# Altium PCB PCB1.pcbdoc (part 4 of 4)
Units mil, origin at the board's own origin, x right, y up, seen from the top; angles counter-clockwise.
Board outline 2559.1 x 3937 mil, 4 copper layers (Top Layer, Inner1, Inner2, Bottom Layer), stack 102.8 mil thick; 377 components, 358 nets, 1639 pads, 361 vias.
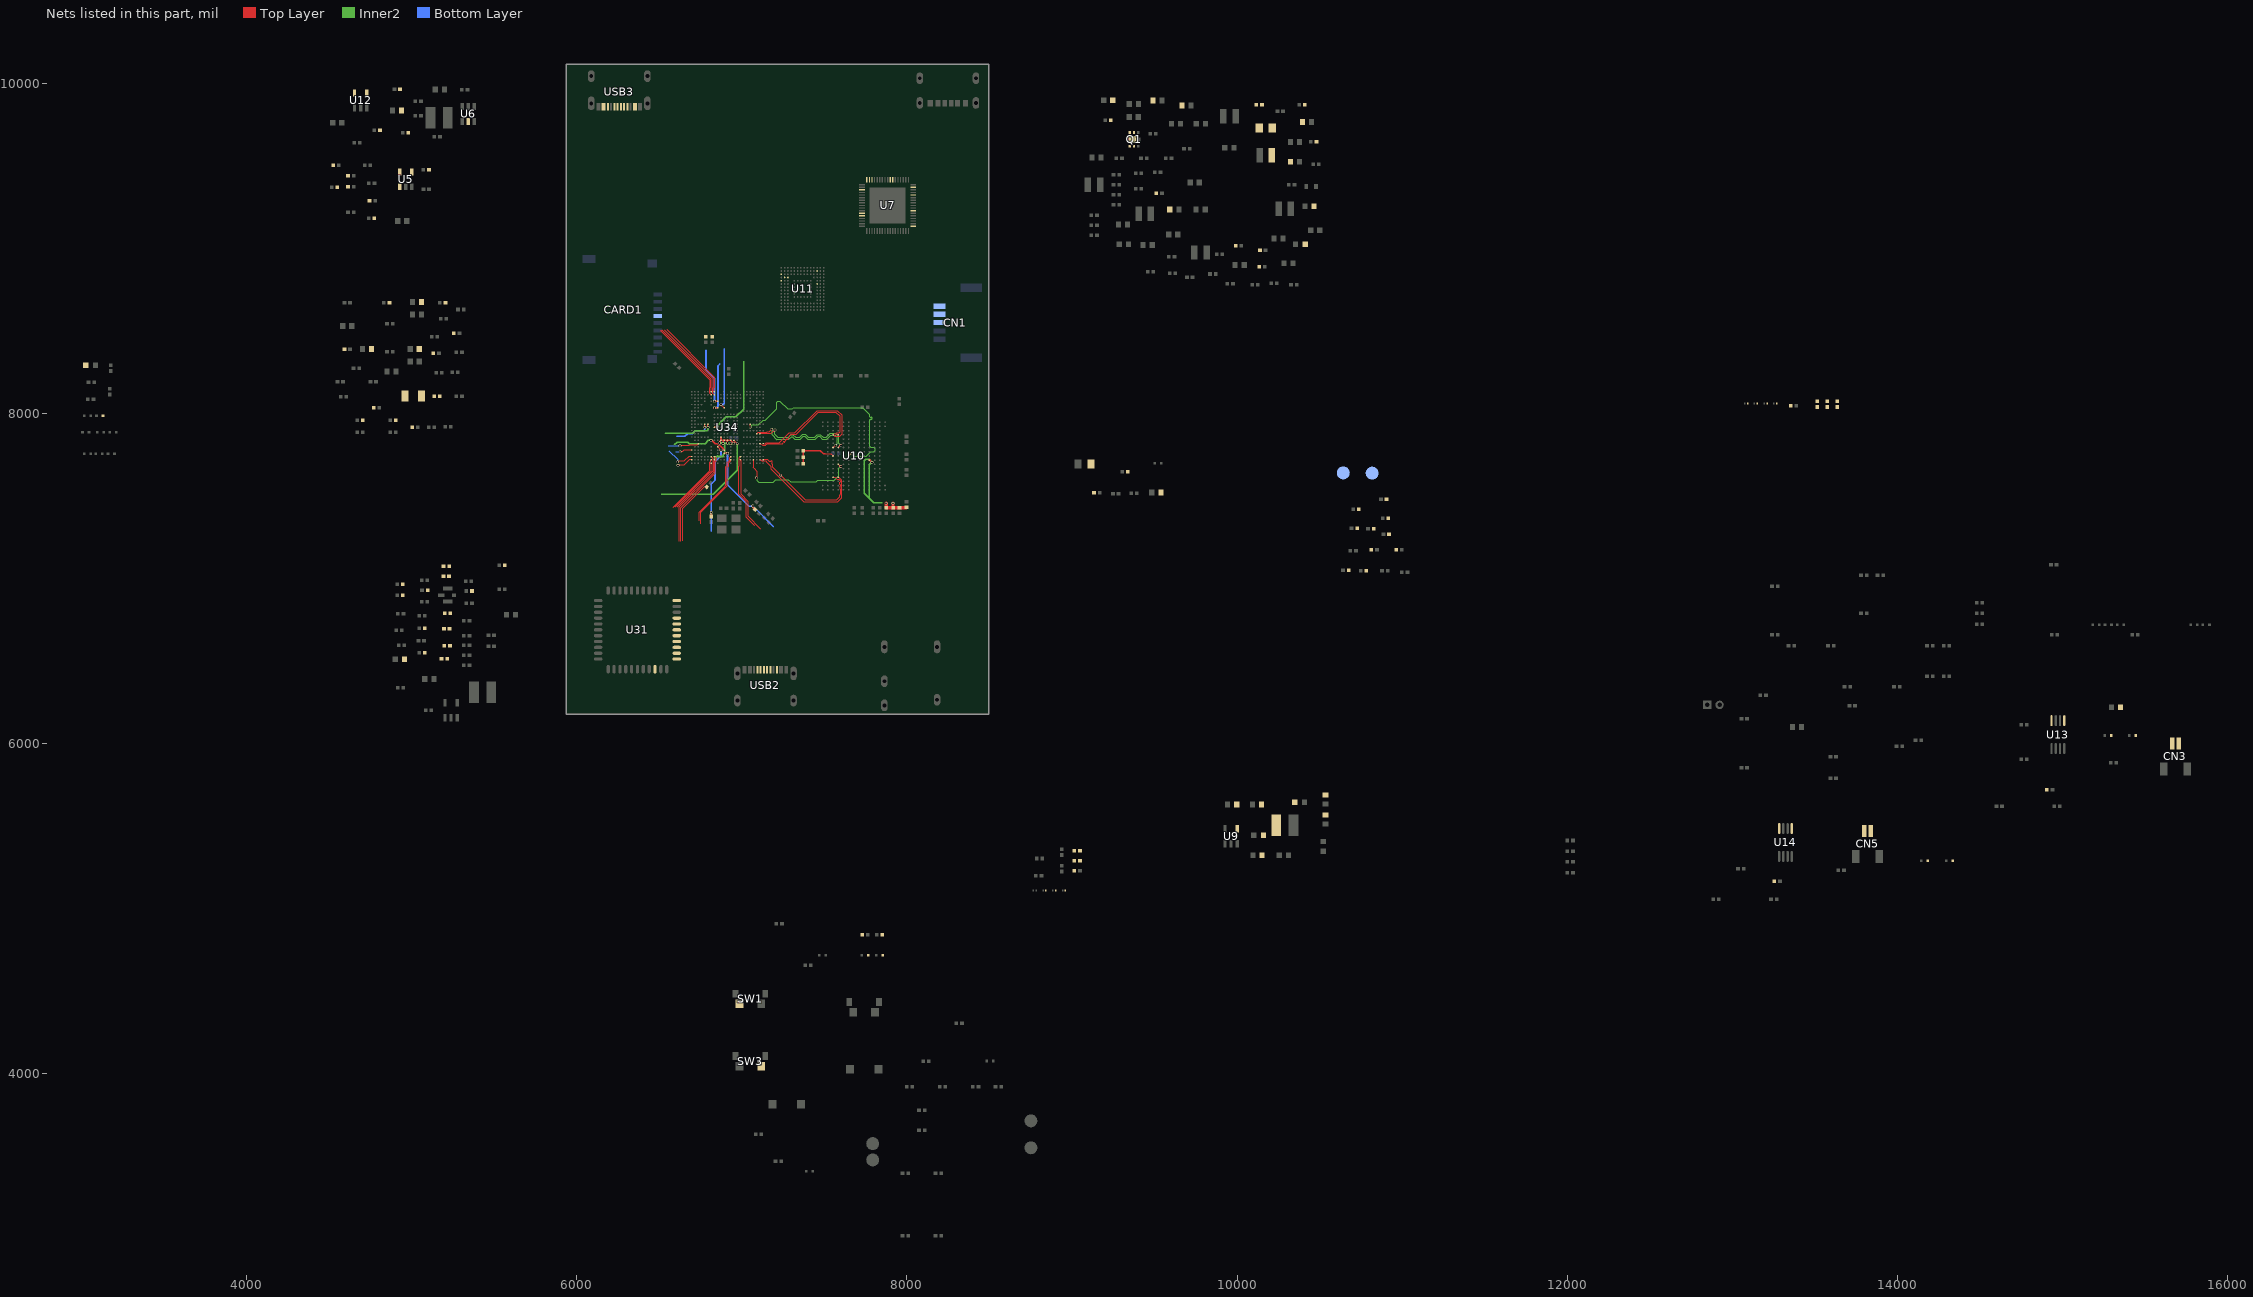
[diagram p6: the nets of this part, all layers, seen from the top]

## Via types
v1: diameter 16, hole 11.8, Top Layer to Bottom Layer, 361 vias

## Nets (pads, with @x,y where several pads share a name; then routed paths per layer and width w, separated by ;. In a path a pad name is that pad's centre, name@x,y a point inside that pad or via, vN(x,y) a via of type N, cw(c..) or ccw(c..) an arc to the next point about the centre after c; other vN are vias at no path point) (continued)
SDQS0P: U10.G10 U34.Y2 | length 749.4
  Top Layer w3.5: U34.Y2@7072.1,7717.2 7071.3,7716.4 7071.3,7670.9 7079.3,7662.9
  Top Layer w4: U34.Y2@7071.5,7717.8 U34.Y2@7072.1,7717.2 ; 7079.3,7662.9 7095.4,7646.8 7095.4,7615.4 v1(7088.9,7608.9) ; U10.G10@7584.9,7690.1 7597.8,7677.2 v1(7600.6,7677.2)
  Inner2 w4: v1(7088.9,7608.9) 7092.5,7605.2 7092.5,7593.3 7102.9,7583 7191.6,7583 7206.9,7598.3 7282.4,7598.3 7296.4,7584.4 7450.3,7584.4 7459.7,7593.7 7562,7593.7 7589.1,7620.8 7589.1,7665.7 v1(7600.6,7677.2)
SDQS1N: U10.D11 U34.AC2 | length 754.6
  Top Layer w4: U34.AC2@7130.6,7717.8 7159.3,7717.8 7167.7,7709.5 ; 7167.72,7709.42 ccw(c7171.4,7713.1) 7175.08,7709.42 ; 7175.12,7709.48 cw(c7178.8,7705.8) 7182.48,7709.48 ; 7182.4,7709.5 7183.6,7708.3 ; 7183.52,7693.62 cw(c7187.2,7697.3) 7183.52,7700.98 ; 7183.6,7693.6 7189.6,7687.5 7189.6,7672.1 v1(7236.5,7625.2) 7387.7,7474.1 7573.9,7474.1 7589.9,7490.1 7589.9,7500.8 7597,7507.9 7597,7540.4 7594,7543.4 7594,7553.5 7597,7556.5 7597,7566.4 7591.7,7571.7 7591.7,7577.7 7597,7583 7597,7591.8 7587.5,7601.2 7575.3,7601.2 7571.3,7605.2 7571.3,7610 7568,7613.3 U10.D11@7553.4,7613.3 ; 7183.58,7701.02 ccw(c7179.9,7704.7) 7183.58,7708.38
SDQS1P: U10.D10 U34.AB2 | length 754.6
  Top Layer w3.5: U34.AB2@7110.9,7717.8 7115.7,7717.8 7125.5,7708 7147.4,7708 7147.9,7707.5
  Top Layer w4: 7147.9,7707.5 7177,7678.4 7177,7662.8 7377,7462.8 7580.7,7462.8 7605,7487 7605,7595.1 7586.8,7613.3 U10.D10@7584.9,7613.3
SDQS2N: U10.P11 U34.AC7 | length 749.1
  Top Layer w4: U34.AC7@7130.6,7816.3 7143.7,7816.3 7147.4,7820 7227.9,7820 7289.3,7881.4 7322.6,7881.4 7457.7,8016.5 7578.4,8016.5 7604.8,7990.1 7604.8,7871.7 7589.9,7856.9 7565.7,7856.9 U10.P11@7553.4,7869.2
SDQS2P: U10.P10 U34.AB7 | length 749.3
  Top Layer w3.5: U34.AB7@7110.9,7816.3 7113.1,7816.3 7115.9,7813.4 7118.3,7813.4 7123.9,7807.8 7126,7807.8 7126.4,7807.4 7126.6,7807.6 7127.2,7807.1 7144.8,7807.1 7148.9,7811.2 7150.8,7811.2
  Top Layer w4: 7150.8,7811.2 7246.4,7811.2 7248.6,7813.4 ccw(c7246.5,7815.5) 7248.62,7817.62 ; 7248.58,7817.68 cw(c7250.7,7819.8) 7248.58,7821.92 7252.9,7826.1 cw(c7255,7824) 7257.12,7826.12 ; 7257.08,7826.18 ccw(c7259.2,7828.3) 7261.32,7826.18 ; 7261.3,7826.1 7265.6,7830.4 ccw(c7263.5,7832.5) 7265.62,7834.62 cw(c7267.7,7836.7) 7265.58,7838.82 ; 7265.6,7838.9 7269.8,7843.1 ; 7269.88,7843.12 cw(c7272,7841) 7274.12,7843.12 ccw(c7276.2,7845.2) 7278.32,7843.08 7280.7,7845.4 7280.7,7852.6 7298.5,7870.4 7327.7,7870.4 7461.5,8004.3 7573.8,8004.3 7596.8,7981.3 7596.8,7888 7592,7883.3 7572.5,7883.3 7567.6,7878.4 7567.6,7873.8 7572.2,7869.2 U10.P10@7584.9,7869.2
SDQS3N: U10.L11 U34.AA10 | length 672.4
  Top Layer w3.5: U34.AA10@7091.9,7876.5 7100.6,7885.1 7150.4,7885.1
  Top Layer w4: 7150.5,7885.1 7164,7885.1 7181.1,7902.3 v1(7181.3,7902.3) ; U10.L11@7553.4,7792.5 7566.3,7805.4 v1(7569.1,7805.4)
  Inner2 w4: v1(7181.3,7902.3) 7181.1,7902.1 7181.1,7871.4 7212.7,7839.9 7282.8,7839.9 7298.9,7855.9 7308.9,7855.9 7325,7839.9 7350.9,7839.9 7369.9,7858.9 7383.9,7858.9 7402.9,7839.9 7444,7839.9 7461.1,7857 7474.5,7857 7491.6,7839.9 7513.6,7839.9 7536,7862.3 7571.2,7862.3 7579.8,7853.7 7579.8,7816 v1(7569.1,7805.4)
SDQS3P: U10.L10 U34.AB10 | length 664.5
  Top Layer w4: U34.AB10@7110.9,7875.3 7177.5,7875.3 7200.7,7898.5 v1(7201.4,7898.5) v1@7201.8,7898.5 ; U10.L10@7584.9,7792.5 7597.8,7805.4 v1(7600.6,7805.4)
  Inner2 w4: v1(7201.4,7898.5) 7201.4,7871.4 7222.1,7850.8 7278.3,7850.8 7295.1,7867.5 7313.7,7867.5 7330.5,7850.8 7348,7850.8 7366.7,7869.5 7388.5,7869.5 7407.3,7850.8 7438.4,7850.8 7455.3,7867.6 7479.4,7867.6 7496.3,7850.8 7508.4,7850.8 7532.9,7875.2 7575.2,7875.2 7589.2,7861.3 7589.2,7816.8 v1(7600.6,7805.4)
SODT0: U10.J8 U34.W13 | length 1320
  Top Layer w4: v1(7051.6,7915.7) U34.W13@7051.6,7934.1 ; U10.J8@7647.9,7741.3 7660.8,7754.2 v1(7663.6,7754.2)
  Inner2 w4: v1(7051.6,7915.7) 7065.2,7929.3 7101,7929.3 7130,7958.3 7143.4,7958.3 7211.8,8026.7 7211.8,8065.8 7219.7,8073.7 7230.9,8073.7 7278.7,8025.9 7306.3,8025.9 7314,8033.6 7734.5,8033.6 7773.5,7994.6 7773.5,7983.1 ccw(c7780.5,7983.1) 7780.5,7976.1 7784.1,7976.1 cw(c7784.1,7969.1) 7784.1,7962.1 7780.5,7962.1 ccw(c7780.5,7955.1) 7773.5,7955.1 7773.5,7802.4 7783.2,7792.7 7799.4,7792.7 7805.3,7786.9 7805.3,7772.8 7797.3,7764.8 7778.4,7764.8 7750.8,7737.2 7680.6,7737.2 v1(7663.6,7754.2)
SPKL+: CN5.2 D31.2 U14.8
SPKL-: CN5.1 D32.2 R130.1 U14.5
SPKR+: CN3.2 D27.2 U13.8
SPKR-: CN3.1 D28.2 R126.1 U13.5
SVREF: C135.2 C136.2 R83.1 R85.2 U10.H4 | length 811.7
  Top Layer w11.8: U10.H4@7773.8,7715.7 7776.7,7715.7 v1(7789.6,7702.8)
  Top Layer w20: v1(7874.9,7455) C135.2@7874.9,7428.3 C136.2@7916.9,7428.3 ; v1(7916.9,7454.8) C136.2@7916.9,7428.3 ; R83.1@7998.3,7429.7 7996.9,7428.3 R85.2@7955.9,7428.3 C136.2@7916.9,7428.3
  Inner2 w8: 7852.7,7457.3 7800.4,7457.3 7772.1,7485.6 ; 7772.1,7485.6 7742.5,7515.2 7742.5,7711 7752.8,7721.2 7771.2,7721.2 v1(7789.6,7702.8) 7773.9,7687.2 7773.9,7487.4 7772.1,7485.6
SWOUT: C84.1 U7.18
TS: CN1.3 R40.2 U7.30
TWI0-CLK: U34.C7 | length 188.7
  Top Layer w3.5: 6682.7,7806.4 6727,7806.4 U34.C7@6736.9,7816.3
  Top Layer w4: v1(6626.6,7802.3) 6630.7,7806.4 6682.7,7806.4
  Bottom Layer w4: 6554,7802.3 v1(6626.6,7802.3)
TWI0-SDA: U34.A5 | length 101.3
  Top Layer w4: v1(6627.4,7766.3) 6640,7766.3 6650.3,7776.7 6697.3,7776.7 U34.A5@6697.5,7776.9
  Bottom Layer w4: 6600.6,7766.3 v1(6627.4,7766.3)
USB0-DM: R62.1 R105.2 U34.G22 | length 518.7
  Top Layer w3.5: 6805.8,8154.8 6805.8,8121.4 U34.G22@6815.6,8111.5
  Top Layer w4: 6506.2,8502 6805.8,8202.5 6805.8,8154.8
USB0-DM-I: D21.2 R105.1 USB3.A7 USB3.B7
USB0-DP: R60.1 R106.2 U34.G23 | length 494.4
  Top Layer w3.5: U34.G23@6815.6,8131.2 6815.6,8154.4
  Top Layer w4: 6519.6,8503 6815.6,8207 6815.6,8154.4
USB0-DP-I: D20.2 R106.1 USB3.A6 USB3.B6
USB0-ID: D19.2 R107.1 R108.1 USB3.A5 USB3.B5
USB0-ID-SOC: R107.2 U34.A3 | length 187.4
  Top Layer w3.5: 6653.1,7711.8 6678.6,7737.3 U34.A3@6696.7,7737.3
  Top Layer w4: v1(6611.8,7705.9) 6617.4,7705.9 6623.3,7711.8 6653.1,7711.8
  Bottom Layer w4: 6558.8,7773.4 6611.8,7720.5 v1(6611.8,7705.9)
USB1-CC: D15.2 R99.1 USB2.A5 USB2.B5
USB1-DM: R97.2 U34.H22 | length 518.5
  Top Layer w3.5: 6825.5,8154.4 6825.5,8121.3 U34.H22@6835.3,8111.5
  Top Layer w4: 6532.3,8504.5 6825.5,8211.3 6825.5,8154.4
USB1-DM-I: D17.2 R97.1 USB2.A7 USB2.B7
USB1-DP: R98.2 U34.H23 | length 496.5
  Top Layer w3.5: U34.H23@6835.3,8131.2 6835.3,8154.1
  Top Layer w4: 6544.7,8507.4 6835.3,8216.7 6835.3,8154.1
USB1-DP-I: D16.2 R98.1 USB2.A6 USB2.B6
USB1-DRVVBUS: R104.2 U12.4 U34.A2 | length 101.9
  Top Layer w3.5: v1(6614.4,7684.6) 6649.9,7684.6 6683.6,7718.3 U34.A2@6696.4,7718.3
  Bottom Layer w4: v1@6608.5,7684.6 v1(6614.4,7684.6)
USBVBUS: C82.1 C148.2 C149.1 D18.2 R34.2 U5.1 U7.54 USB3.A4 USB3.A9 USB3.B4 USB3.B9
VBAT: C74.1 C75.2 CN1.1 CN1.2 R51.2 U7.64
VBAT_EXT: C75.1 C81.1 C83.1 L5.2 Q1.1 Q1.2 Q1.5 Q1.6 Q1.7 R51.1 U7.63
VBUSEN: R39.2 U5.4 U7.51
VCC3V3_SYS: C118.2 C119.2 C120.2 L11.2 R189.2
VCC-5V: C61.2 C62.2 C115.2 C116.2 C147.2 L10.2 R41.2 R102.2 R188.1 U5.5 U6.2 U9.4 U12.5
VCC-CARD-3V3: CARD1.4 D13.2 R92.1
VCC-MOTOR: R74.2
VCC-PC: C53.1 C141.2 C142.1 R43.2 R49.2 R94.1 R95.1 U11.C6 U11.M4 U11.N4 U11.P3 U11.P5 U34.L18 | length 380.5
  Top Layer w4: v1(6874.7,8052.5) U34.L18@6894.4,8032.8
  Bottom Layer w10: v1(6874.7,8052.5) 6887.7,8052.5 6894.9,8059.7 6894.9,8389.2
VCC-PG: C58.1 C162.2 R64.1 R65.1 R149.2 R150.2 R151.2 R152.2 R153.2 R154.2 R155.2 R156.2 R160.2 U31.22 U34.J6 | length 565.8
  Top Layer w4: U34.J6@6855.1,7796.3 v1(6874.7,7776.7)
  Top Layer w10: C58.1@6815.6,7375 v1(6815.6,7399.1)
  Bottom Layer w10: 6815.6,7287.2 v1(6815.6,7399.1) 6815.6,7571.8 6838.2,7594.4 6838.2,7706.9 6874.7,7743.4 v1(6874.7,7776.7)
VCC-PL: C57.1 R182.2 R183.2 U34.L4 | length 625.7
  Top Layer w4: U34.L4@6894.4,7757.2 v1@6914.1,7757.2
  Top Layer w10: v1(7067.5,7438) 7067.5,7429.7 C57.1@7085,7412.2
  Bottom Layer w10: v1(6914,7757.2) 6914,7566.7 7043.1,7437.7 7068.1,7437.7 7191.8,7314
VCC-RTC: C34.1 C89.2 R50.2 U7.49 U34.L5 | length 343.2
  Top Layer w4: v1(6814.1,7835.9) v1@6817.1,7835.9 ; 6852.2,7813.9 6862.2,7803.9 6867.3,7803.9
  Top Layer w8: v1@6817.1,7835.9 6817.3,7835.9 6839.3,7813.9 6852.2,7813.9 ; 6869.4,7803.9 6894.4,7778.9 U34.L5@6894.4,7776.9
  Inner2 w8: 6593.1,7808.6 6609.3,7824.7 6673.4,7824.7 6682.1,7816.1 6778.4,7816.1 6798.3,7835.9 v1(6814.1,7835.9)
VCC-USB: C30.1 R48.2 U34.J20 | length 351.1
  Top Layer w10: v1(6835.3,8072.2) U34.J20@6855,8072.2
  Bottom Layer w10: 6783.7,8382.2 6783.7,8263.4 6835.3,8211.8 v1(6835.3,8072.2)
VCC-WIFI: C161.2 R167.2 R168.2 U31.9
VDD-CPU: C36.1 C37.2 C38.2 C39.2 C40.2 C41.2 R61.2 U34.K8 U34.K9 U34.L8 U34.M8 U34.N8 | length 390.8
  Top Layer w10: v1(6866.5,7819.9) 6866.5,7827.8 U34.K8@6874.7,7835.9 ; U34.K9@6874.7,7855.6 U34.K8@6874.7,7835.9 ; v1(6888.1,7816.7) 6888.1,7829.7 U34.L8@6894.4,7835.9 ; v1(6913.6,7818.9) 6913.6,7835.5 U34.M8@6914,7835.9 ; v1(6951.4,7817.8) 6934.2,7835 6932.8,7835 U34.N8@6933.7,7835.9 U34.M8@6914,7835.9 ; U34.K8@6874.7,7835.9 U34.L8@6894.4,7835.9 ; U34.L8@6894.4,7835.9 U34.M8@6914,7835.9
  Inner2 w10: 6843,7731.7 6854.1,7742.9 6858.6,7738.4 6889,7738.4 6889,7749.1 6897.1,7757.2 6897.1,7816.5 ; v1(6866.5,7819.9) 6885,7819.9 v1(6888.1,7816.7) 6888.4,7816.5 6897.1,7816.5 ; v1(6951.4,7817.8) 6949.9,7816.3 v1(6932.9,7816.3) 6916.2,7816.3 v1(6913.6,7818.9) 6899.5,7818.9 6897.1,7816.5
  Inner2 w20: 6840.4,7729.1 6843,7731.7
VDD-CPUFB: U3.1 U7.41 U7.42 U34.P8 | length 709.5
  Top Layer w4: U34.P8@6953.4,7835.9 v1@6973.1,7816.3
  Inner2 w8: 6513.8,7509.3 6828.9,7509.3 6973.1,7653.5 v1(6973.1,7816.2)
VDD-SYSFB: U4.1 U7.24 U34.H12 | length 518.3
  Top Layer w4: U34.H12@6835.3,7914.7 v1(6855,7914.7)
  Inner2 w8: v1(6855,7914.7) 6855,7926.7 6906.4,7978.1 6963.8,7978.1 7011.3,8025.6 7011.3,8314.9
VDD-USB: C31.1 R59.2 R63.2 U34.J18 | length 305
  Top Layer w10: v1(6835.3,8032.8) U34.J18@6855,8032.8
  Bottom Layer w10: v1(6835.3,8032.8) 6846,8032.8 6856.4,8043.2 6856.4,8286.5 6868.1,8298.2
VDDI-EMMC: C139.2 C140.1 U11.C2
VINT: C88.2 R52.1 U7.50
VOL+: D34.2 R134.1 SW1.3
VOL-: D35.2 R135.2 SW3.4
VRA1: C25.2 U34.F13 | length 300.9
  Top Layer w4: v1(6795.9,7914.7) U34.F13@6795.9,7934.4
  Inner2 w10: 6537.9,7878.1 6703.1,7878.1 6718.5,7893.6 6788.5,7893.6 6795.9,7901 v1(6795.9,7914.7)
VRA2: C26.2 U34.E13 | length 221.2
  Top Layer w4: v1(6776.3,7914.7) U34.E13@6776.3,7934.4
  Bottom Layer w10: 6605.9,7859.7 6655.5,7859.7 6672.5,7876.7 6702.4,7876.7 6720.5,7894.8 6770.5,7894.8 6776.3,7900.5 v1(6776.3,7914.7)
VREF: C102.1 U7.33
VREFDQ: C121.2 R84.1 R86.2 U10.J11 | length 274
  Top Layer w4: 7506.5,7754.4 7540.2,7754.4 U10.J11@7553.4,7741.3
  Top Layer w10: R84.1@7372.7,7693.3 R86.2@7372.7,7733.3 C121.2@7372.7,7773.3 7476.5,7773.3 7495.3,7754.4 7506.5,7754.4
WL-PMU-EN: R157.2 U31.12 U34.N3 | length 469.6
  Top Layer w3.5: 6891.2,7549.6 6901.8,7560.3 6901.8,7671.6 6910.7,7680.5 6910.7,7699.8 6923.8,7712.9 6923.8,7727.6 U34.N3@6933.7,7737.5
  Top Layer w4: 6740.2,7348.1 6740.2,7398.7 6891.2,7549.6
WL-SDIO-CLK: R32.1 R154.1 U31.17 | length 393.9
  Top Layer w4: 6642.9,7229.2 6642.9,7423.9 6772.7,7553.7 R32.1@6788.3,7553.7
WL-SDIO-CMD: R153.1 U31.16 U34.H2 | length 582.4
  Top Layer w3.5: 6821,7631.4 6831.8,7642.2 6831.8,7709.4 6835.3,7712.9 U34.H2@6835.3,7717.8
  Top Layer w4: 6619.4,7224.8 6619.4,7429.8 6821,7631.4
WL-SDIO-D0: R155.1 U31.18 U34.G1 | length 356
  Top Layer w3.5: 6804.9,7639.1 6815.6,7649.8 U34.G1@6815.6,7698.1
  Top Layer w4: 6598,7432.2 6804.9,7639.1
WL-SDIO-D1: R156.1 U31.19 U34.G3 | length 400.6
  Top Layer w3.5: 6814.1,7637 6824.8,7647.7 6824.8,7714.2 6825.4,7714.8 6825.4,7727.7 U34.G3@6815.6,7737.5
  Top Layer w4: 6608.1,7431 6814.1,7637
WL-SDIO-D2: R151.1 U31.14 U34.G2 | length 384.4
  Top Layer w3.5: 6799.5,7644.4 6806.5,7651.4 6806.5,7703 6812.8,7709.3 6812.8,7715.4 U34.G2@6815.5,7718
  Top Layer w4: 6584.4,7429.4 6799.5,7644.4
WL-SDIO-D3: R152.1 U31.15 U34.H3 | length 605.4
  Top Layer w3.5: 6828.6,7624.8 6838.8,7635.1 6838.8,7705.9 6845.2,7712.2 6845.2,7727.6 U34.H3@6835.3,7737.5
  Top Layer w4: 6632.2,7224.4 6632.2,7428.4 6828.6,7624.8
WL-WAKE-AP: U31.13 U34.N2 | length 464.1
  Top Layer w3.5: 6896.9,7544.8 6908.8,7556.7 6908.8,7668.7 6917.7,7677.6 6917.7,7696.9 6930.8,7710 6930.8,7714.9 U34.N2@6933.7,7717.8
  Top Layer w4: 6749.7,7329.9 6749.7,7397.5 6896.9,7544.8
X32KIN: C19.1 R26.2 U34.T2 X2.2 | length 465.9
  Top Layer w4: U34.T2@6992.8,7717.8 6993,7717.7 6993,7511.6 7036.9,7467.7 7036.9,7377.9 7113,7301.7
X32KOUT: C23.1 R26.1 U34.T3 X2.1 | length 462.6
  Top Layer w3.5: 6982.9,7680 6982.9,7727.7 U34.T3@6992.8,7737.5
  Top Layer w4: 6982.9,7680 6982.9,7508.3 7027.5,7463.7 7027.5,7370.8 7079.4,7319
pads on no net: U7.5 U7.9 U7.10 U10.A1 U10.A2 U10.A12 U10.A13 U10.B1 U10.B13 U10.C4 U10.K9 U10.R3 U10.T1 U10.T13 U10.U1 U10.U2 U10.U12 U10.U13 U11.A1 U11.A2 U11.A7 U11.A8 U11.A9 U11.A10 U11.A11 U11.A12 U11.A13 U11.A14 U11.B1 U11.B7 U11.B8 U11.B9 U11.B10 U11.B11 U11.B12 U11.B13 U11.B14 U11.C1 U11.C3 U11.C5 U11.C7 U11.C8 U11.C9 U11.C10 U11.C11 U11.C12 U11.C13 U11.C14 U11.D1 U11.D2 U11.D3 U11.D4 U11.D12 U11.D13 U11.D14 U11.E1 U11.E2 U11.E3 U11.E5 U11.E8 U11.E9 U11.E10 U11.E12 U11.E13 U11.E14 U11.F1 U11.F2 U11.F3 U11.F10 U11.F12 U11.F13 U11.F14 U11.G1 U11.G2 U11.G3 U11.G10 U11.G12 U11.G13 U11.G14 U11.H1 U11.H2 U11.H3 U11.H12 U11.H13 U11.H14 U11.J1 U11.J2 U11.J3 U11.J12 U11.J13 U11.J14 U11.K1 U11.K2 U11.K3 U11.K6 U11.K7 U11.K10 U11.K12 U11.K13 U11.K14 U11.L1 U11.L2 U11.L3 U11.L12 U11.L13 U11.L14 U11.M1 U11.M2 U11.M3 U11.M7 U11.M8 U11.M9 U11.M10 U11.M11 U11.M12 U11.M13 U11.M14 U11.N1 U11.N3 U11.N6 U11.N7 U11.N8 U11.N9 U11.N10 U11.N11 U11.N12 U11.N13 U11.N14 U11.P1 U11.P2 U11.P7 U11.P8 U11.P9 U11.P10 U11.P11 U11.P12 U11.P13 U11.P14 U31.8 U31.10 U31.11 U31.21 U31.30 U31.32 U31.35 U31.37 U31.38 U31.39 U31.40 U34.A14 U34.AA20 U34.AB12 U34.AB15 U34.AB16 U34.AB17 U34.AB20 U34.AC13 U34.AC17 U34.AC19 U34.AC21 U34.B7 U34.B14 U34.D19 U34.F11 U34.G19 U34.G21 U34.L2 U34.L19 U34.L23 U34.M21 U34.M22 U34.N20 U34.R3 U34.U17 U34.W15 U34.Y15 U34.Y17 USB2.A8 USB2.B8 USB3.A8 USB3.B8

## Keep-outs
Top Layer:
  region: 6666.9,8154.9 6666.9,7685.5 7158.3,7685.5 7158.3,8154.9
Inner2:
  region: 7091.8,8053 7091.8,8112.7 7182,8202.9 7875.1,8202.9 7960.3,8117.7 7960.3,7576.8 7915.5,7532 7130,7532 7049.3,7612.7 7049.3,7656.8 7032,7674 7032,7703.9 6985.3,7750.6 6985.3,7946.6
Board Outline Layer:
  the board outline again, w10

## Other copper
Top Layer:
  drawing of 748 lines, arcs and shapes, not listed
Inner1:
  region net AGND: 6743.6,7873 6748,7883 6750.9,7882.7 6752.4,7882.6 6753.6,7882.8 6749.2,7872.1 6748.8,7872.8 6748.3,7873.3 6747.7,7873.4 6747,7873.5 6745.5,7873.2
  region net DCDC5: 7323.2,7715.6 7323.2,7705.6 7320.2,7705.6 7318.8,7705.3 7317.6,7704.6 7317.6,7716.6 7318.8,7715.8 7320.2,7715.5
  region net DCDC5: 7488,7583.8 7488,7573.8 7485,7573.9 7483.7,7573.6 7482.4,7572.8 7482.4,7584.8 7483.7,7584 7485,7583.8
  region net DCDC5: 7493.7,7830.5 7493.7,7820.5 7490.7,7820.6 7489.3,7820.3 7488.1,7819.5 7488.1,7831.5 7489.3,7830.7 7490.7,7830.5
  region net DCDC5: 7498.5,7899.3 7498.5,7889.3 7495.5,7889.4 7494.2,7889.1 7492.9,7888.3 7492.9,7900.3 7494.2,7899.6 7495.5,7899.3
  region net DCDC5: 7509.7,7635.1 7499.7,7635.1 7499.8,7638.2 7499.5,7639.5 7498.7,7640.7 7510.7,7640.7 7510,7639.5 7509.7,7638.2
  region net DCDC5: 7498.4,7706.9 7505.5,7714 7507.6,7711.8 7508.7,7711.1 7510.1,7710.7 7501.7,7702.2 7501.3,7703.7 7500.6,7704.8
  region net DCDC5: 7508.9,7657.3 7516,7650.2 7513.8,7648.1 7513.1,7647 7512.7,7645.5 7504.2,7654 7505.7,7654.4 7506.8,7655.1
  region net DCDC5: 7511.1,7789.4 7518.2,7782.3 7516,7780.2 7515.3,7779.1 7514.9,7777.6 7506.4,7786.1 7507.9,7786.5 7509,7787.2
  region net DCDC5: 7520.9,7698.6 7513.8,7691.5 7511.7,7693.7 7510.6,7694.4 7509.1,7694.8 7517.6,7703.2 7518,7701.8 7518.7,7700.7
Inner2:
  region net SDQ0: 7080.6,7791 7077.6,7788.4 7076.8,7789.1 7076,7789.5 7075.3,7789.7 7074.5,7789.7 7072.9,7789.6 7070.8,7789.6 7079.5,7797.9 7079.4,7795.9 7079.3,7794.1 7079.4,7793.4 7079.6,7792.6 7080,7791.8
  region net $2N5257: 7077.8,8041.9 7080.6,8039.1 7080,8038.3 7079.6,8037.5 7079.4,8036.8 7079.3,8036 7079.5,8034.3 7079.5,8032.3 7071,8040.8 7073.1,8040.7 7074.7,8040.6 7075.5,8040.7 7076.3,8040.8 7077,8041.2
  region net SDQS0P: 7094.5,7601.3 7090.5,7595.8 7090.4,7596.7 7090.1,7597.6 7089.7,7598.5 7089.1,7599.2 7087.6,7600.5 7085.9,7601.4 7096.6,7606.9 7096.1,7605.5 7095.4,7604.1 7094.8,7602.8
  region net SA5: 7083.4,8000.2 7080.8,7992 7079.7,7990.7 7079,7989.7 7078.4,7988.6 7077.2,7987.3 7076.5,7999.1 7077.3,7998.6 7078.2,7998.4 7079.1,7998.3 7080,7998.4 7081.8,7999
  region net SDQS0N: 7105.6,7602.5 7105.1,7607.6 7105.9,7608.9 7106.4,7610.3 7106.8,7611.8 7107.3,7613.3 7111.6,7602.1 7109.9,7602.8 7108.4,7603.3 7107.6,7603.4 7106.9,7603.3 7106.2,7603
  region net SDQ24: 7082.4,7878.6 7082.4,7874.6 7081.4,7874.5 7080.6,7874.3 7079.9,7873.9 7079.3,7873.4 7078.2,7872.1 7076.8,7870.6 7076.8,7882.6 7078.2,7881.1 7079.3,7879.9 7079.9,7879.3 7080.6,7878.9 7081.4,7878.7
  region net FLDO1: 7159.1,7425.2 7159.1,7415.2 7156.1,7415.3 7154.8,7415 7153.5,7414.2 7153.5,7426.2 7154.8,7425.5 7156.1,7425.2
  region net SDQ7: 7147.3,7514.2 7147.3,7510.2 7146.3,7510.1 7145.5,7509.8 7144.8,7509.4 7144.3,7508.9 7143.2,7507.6 7141.7,7506.2 7141.7,7518.2 7143.2,7516.7 7144.3,7515.4 7144.8,7514.9 7145.5,7514.5 7146.3,7514.3
  region net SDQ6: 7144.8,7539.9 7144.8,7535.9 7143.8,7535.8 7143,7535.5 7142.3,7535.1 7141.7,7534.6 7140.6,7533.3 7139.2,7531.9 7139.2,7543.9 7140.6,7542.4 7141.7,7541.1 7142.3,7540.6 7143,7540.2 7143.8,7540
  region net SA9: 7173.8,8170.1 7176.6,8167.2 7175.9,8166.4 7175.5,8165.7 7175.3,8164.9 7175.3,8164.2 7175.4,8162.5 7175.4,8160.4 7167,8169 7169,8168.9 7170.7,8168.8 7171.5,8168.9 7172.3,8169 7173,8169.4
  region net SDQS3P: 7203.4,7887.6 7199.4,7887.6 7199.3,7888.6 7199.1,7889.4 7198.7,7890.1 7198.2,7890.7 7196.9,7891.8 7195.4,7893.2 7207.4,7893.2 7206,7891.8 7204.7,7890.7 7204.2,7890.1 7203.8,7889.4 7203.5,7888.6
  region net SDQ28: 7208.6,7916.8 7208.8,7910.9 7208.1,7911.5 7207.3,7911.9 7206.4,7912.2 7205.5,7912.3 7203.5,7912.1 7201.6,7911.7 7206.5,7922.6 7207,7921.2 7207.3,7919.6 7207.8,7918 7208.1,7917.4
  region net SDQ30: 7231.2,7925.1 7231.2,7921.1 7230.2,7921 7229.4,7920.7 7228.7,7920.3 7228.1,7919.8 7227,7918.5 7225.6,7917.1 7225.6,7929.1 7227,7927.6 7228.1,7926.3 7228.7,7925.8 7229.4,7925.4 7230.2,7925.2
  region net SCKP: 7334.4,8099.9 7332.1,8091.9 7331,8090.6 7330.5,8089.6 7330,8088.5 7329,8087.2 7327.6,8098.9 7328.4,8098.4 7329.2,8098.2 7330.2,8098.1 7331.1,8098.2 7332.9,8098.8
  region net SCKN: 7344.7,8087.8 7347.5,8085 7347.2,8084.5 7347.1,8083.9 7347.2,8082.4 7347.5,8080.9 7347.7,8079.5 7339.2,8088 7340.5,8087.9 7342.1,8087.6 7343.6,8087.4 7344.2,8087.5
  region net $2N5257: 7357.8,8223.1 7357.8,8227.1 7358.8,8227.2 7359.6,8227.4 7360.3,8227.8 7360.9,8228.3 7362,8229.6 7363.4,8231.1 7363.4,8219.1 7362,8220.5 7360.9,8221.8 7360.3,8222.3 7359.6,8222.7 7358.8,8223
  region net SDQ27: 7531.4,7794.6 7528.5,7797.4 7529.2,7798.2 7529.6,7798.9 7529.8,7799.7 7529.8,7800.5 7529.7,7802.2 7529.7,7804.2 7538.1,7795.7 7536.1,7795.8 7534.4,7795.9 7533.6,7795.8 7532.9,7795.6 7532.1,7795.2
  region net SDQ0: 7528.5,7683.7 7531.4,7686.5 7532.1,7685.9 7532.9,7685.5 7533.6,7685.3 7534.4,7685.2 7536.1,7685.3 7538.1,7685.4 7529.7,7676.9 7529.7,7678.9 7529.8,7680.6 7529.8,7681.4 7529.6,7682.2 7529.2,7682.9
  region net SDQ3: 7528.5,7658.1 7531.4,7660.9 7532.1,7660.3 7532.9,7659.9 7533.6,7659.7 7534.4,7659.6 7536.1,7659.8 7538.1,7659.8 7529.7,7651.3 7529.7,7653.3 7529.8,7655 7529.8,7655.8 7529.6,7656.6 7529.2,7657.3
  region net SDQ25: 7559.8,7822 7556.9,7824.8 7557.6,7825.6 7558,7826.3 7558.2,7827.1 7558.2,7827.9 7558.1,7829.6 7558.1,7831.6 7566.6,7823.1 7564.5,7823.1 7562.8,7823.3 7562.1,7823.2 7561.3,7823 7560.6,7822.6
  region net SDQS3N: 7575.4,7814.5 7578.2,7811.6 7577.6,7810.9 7577.2,7810.1 7577,7809.3 7576.9,7808.6 7577.1,7806.9 7577.1,7804.9 7568.6,7813.3 7570.6,7813.3 7572.3,7813.2 7573.1,7813.2 7573.9,7813.4 7574.6,7813.8
  region net SDQS0N: 7578.2,7670.9 7575.4,7668.1 7574.6,7668.7 7573.9,7669.1 7573.1,7669.3 7572.3,7669.4 7570.6,7669.3 7568.6,7669.2 7577.1,7677.7 7577.1,7675.7 7576.9,7674 7577,7673.2 7577.2,7672.5 7577.6,7671.7
  region net ALDO2: 7586.8,7971.9 7586.8,7960.1 7585.1,7960.4 7583.7,7960.8 7583.2,7960.9 7582.6,7960.8 7581.9,7960.6 7581.2,7960 7581.2,7972 7581.9,7971.5 7582.6,7971.3 7583.2,7971.2 7583.7,7971.3 7585.1,7971.7
  region net ALDO2: 7594.6,7515.5 7584,7504.9 7579.4,7509.2 7576.9,7511.4 7588.2,7522.7 7590.4,7520.1
  region net SDQS0P: 7594.3,7668.1 7591.5,7670.9 7592.1,7671.7 7592.5,7672.5 7592.7,7673.2 7592.8,7674 7592.7,7675.7 7592.6,7677.7 7601.1,7669.2 7599.1,7669.3 7597.4,7669.4 7596.6,7669.3 7595.9,7669.1 7595.1,7668.7
  region net SDQS3P: 7591.5,7811.6 7594.3,7814.5 7595.1,7813.8 7595.9,7813.4 7596.6,7813.2 7597.4,7813.2 7599.1,7813.3 7601.1,7813.3 7592.6,7804.9 7592.7,7806.9 7592.8,7808.6 7592.7,7809.3 7592.5,7810.1 7592.1,7810.9
  region net SDQ30: 7623,7837 7625.8,7839.9 7626.6,7839.2 7627.4,7838.8 7628.1,7838.6 7628.9,7838.6 7630.6,7838.7 7632.6,7838.7 7624.1,7830.2 7624.2,7832.3 7624.3,7834 7624.2,7834.7 7624,7835.5 7623.6,7836.3
  region net SDQ26: 7625.8,7796 7623,7798.9 7623.6,7799.7 7624,7800.4 7624.2,7801.2 7624.3,7801.9 7624.2,7803.6 7624.1,7805.7 7632.6,7797.2 7630.6,7797.2 7628.9,7797.3 7628.1,7797.3 7627.4,7797.1 7626.6,7796.7
  region net SDQ5: 7625.8,7668.3 7623,7671.1 7623.6,7671.9 7624,7672.7 7624.2,7673.4 7624.3,7674.2 7624.2,7675.9 7624.1,7677.9 7632.6,7669.4 7630.6,7669.5 7628.9,7669.6 7628.1,7669.5 7627.4,7669.3 7626.6,7668.9
  region net SDQ24: 7630.1,7867.2 7634.1,7867.2 7634.2,7866.2 7634.5,7865.4 7634.8,7864.7 7635.4,7864.1 7636.6,7863 7638.1,7861.6 7626.1,7861.6 7627.6,7863 7628.9,7864.1 7629.4,7864.7 7629.8,7865.4 7630,7866.2
  region net SDQ7: 7641.2,7645.5 7638.4,7642.7 7637.6,7643.4 7636.9,7643.8 7636.1,7643.9 7635.3,7644 7633.6,7643.9 7631.6,7643.8 7640.1,7652.3 7640,7650.3 7639.9,7648.6 7640,7647.8 7640.2,7647.1 7640.6,7646.3
  region net SDQ2: 7654.5,7657.9 7657.3,7660.7 7658.1,7660.1 7658.8,7659.7 7659.6,7659.5 7660.4,7659.4 7662.1,7659.6 7664.1,7659.6 7655.6,7651.1 7655.7,7653.2 7655.8,7654.8 7655.7,7655.6 7655.5,7656.4 7655.1,7657.1
  region net SDQ29: 7654.5,7837.2 7657.3,7840.1 7658.1,7839.4 7658.8,7839 7659.6,7838.8 7660.4,7838.8 7662.1,7838.9 7664.1,7838.9 7655.6,7830.4 7655.7,7832.5 7655.8,7834.2 7655.7,7834.9 7655.5,7835.7 7655.1,7836.4
  region net SDQM0: 7669.9,7686.3 7672.7,7683.5 7672.1,7682.7 7671.7,7682 7671.5,7681.2 7671.4,7680.4 7671.5,7678.7 7671.6,7676.7 7663.1,7685.2 7665.1,7685.2 7666.8,7685 7667.6,7685.1 7668.3,7685.3 7669.1,7685.7
  region net SDQM3: 7669.9,7814.5 7672.7,7811.6 7672.1,7810.9 7671.7,7810.1 7671.5,7809.3 7671.4,7808.6 7671.5,7806.9 7671.6,7804.9 7663.1,7813.3 7665.1,7813.3 7666.8,7813.2 7667.6,7813.2 7668.3,7813.4 7669.1,7813.8
  region net SODT0: 7672.7,7747.9 7669.9,7745.1 7669.1,7745.7 7668.3,7746.1 7667.6,7746.3 7666.8,7746.4 7665.1,7746.2 7663.1,7746.2 7671.6,7754.7 7671.5,7752.6 7671.4,7751 7671.5,7750.2 7671.7,7749.4 7672.1,7748.7
  region net ALDO2: 7715.3,7961.9 7715.3,7973.7 7717,7973.5 7718.3,7973.1 7718.9,7973 7719.5,7973.1 7720.2,7973.3 7720.9,7973.8 7720.9,7961.8 7720.2,7962.4 7719.5,7962.6 7718.9,7962.7 7718.3,7962.6 7717,7962.2
  region net ALDO2: 7719.9,7487.4 7709.2,7498.1 7713.5,7502.6 7715.7,7505.2 7727,7493.9 7724.4,7491.7
  region net SCKE1: 7749,7786.3 7751.8,7789.1 7752.6,7788.5 7753.4,7788.1 7754.1,7787.9 7754.9,7787.8 7756.6,7788 7758.6,7788 7750.1,7779.5 7750.2,7781.5 7750.3,7783.2 7750.2,7784 7750,7784.8 7749.7,7785.5
  region net SVREF: 7777.9,7511.4 7778.2,7501.8 7779.1,7492.3 7780.6,7482.8 7772.1,7485.6 7764.3,7499.1 7766.7,7503.3 7768.5,7507.8 7769.6,7512.5 7769.9,7517.4 7777.9,7511.4
  region net SVREF: 7779.1,7707.7 7784.7,7713.3 7785.8,7712.5 7787.2,7711.7 7788.7,7711.1 7790.1,7710.8 7781.6,7702.3 7781.3,7703.7 7780.7,7705.2 7779.9,7706.6
  region net SVREF: 7784.7,7692.3 7779.1,7697.9 7779.9,7699 7780.7,7700.4 7781.3,7701.9 7781.6,7703.3 7790.1,7694.8 7788.7,7694.5 7787.2,7693.9 7785.8,7693.2
  region net SA5: 7798.7,7645.3 7795.9,7642.5 7795.1,7643.2 7794.4,7643.6 7793.6,7643.8 7792.8,7643.8 7791.1,7643.7 7789.1,7643.6 7797.6,7652.1 7797.5,7650.1 7797.4,7648.4 7797.5,7647.6 7797.7,7646.9 7798.1,7646.1
  region net SCS1: 7795.9,7815.4 7798.8,7812.6 7798.1,7811.8 7797.7,7811.1 7797.5,7810.3 7797.5,7809.6 7797.6,7807.9 7797.6,7805.8 7789.2,7814.3 7791.2,7814.3 7792.9,7814.2 7793.7,7814.2 7794.4,7814.4 7795.2,7814.8
  region net SCKE0: 7819.1,7790.7 7823.1,7790.7 7823.2,7789.6 7823.4,7788.8 7823.8,7788.2 7824.3,7787.6 7825.6,7786.5 7827.1,7785.1 7815.1,7785.1 7816.5,7786.5 7817.8,7787.6 7818.3,7788.2 7818.7,7788.8 7819,7789.6
  region net SA6: 7827.4,7660.9 7830.2,7658.1 7829.5,7657.3 7829.1,7656.6 7828.9,7655.8 7828.9,7655 7829,7653.3 7829.1,7651.3 7820.6,7659.8 7822.6,7659.8 7824.3,7659.6 7825.1,7659.7 7825.8,7659.9 7826.6,7660.3
  region net SCKN: 7850.6,7764 7854.6,7764 7854.7,7763.1 7854.9,7762.4 7855.3,7761.9 7855.8,7761.5 7857.1,7760.7 7857.8,7760.2 7858.6,7759.5 7846.6,7759.5 7847.3,7760.2 7848,7760.7 7849.3,7761.5 7849.8,7761.9 7850.2,7762.4 7850.5,7763.1
  region net SA7: 7861.2,7630.4 7861.2,7626.4 7860.2,7626.3 7859.4,7626.1 7858.7,7625.7 7858.1,7625.2 7857,7623.9 7855.6,7622.4 7855.6,7634.4 7857,7632.9 7858.1,7631.7 7858.7,7631.1 7859.4,7630.8 7860.2,7630.5
  region net ALDO2: 7810.8,7507.9 7810.8,7503.9 7809.7,7503.8 7808.9,7503.5 7808.3,7503.1 7807.7,7502.6 7806.6,7501.4 7805.2,7499.9 7805.2,7511.9 7806.6,7510.4 7807.7,7509.1 7808.3,7508.6 7808.9,7508.2 7809.7,7508
  region net SA9: 7854.5,7606.7 7861.5,7608.2 7861,7607.4 7860.6,7606.6 7860.1,7604.7 7860.2,7602.8 7860.8,7601 7849.2,7604.1 7850.6,7604.8 7851.9,7605.3 7853.2,7605.8
  region net SA4: 7906.5,7839 7903.7,7841.8 7904.3,7842.6 7904.7,7843.3 7904.9,7844 7904.9,7844.8 7904.7,7846.4 7904.6,7848.4 7913.1,7839.9 7911.1,7840 7909.5,7840.2 7908.7,7840.2 7908,7840 7907.3,7839.6
  region net SA8: 7885.8,7617.6 7890.2,7616.3 7889.6,7615.6 7889.2,7614.8 7889,7613.9 7888.9,7613.1 7889.1,7611.2 7889.4,7609.2 7879.5,7616 7882.8,7616.5 7884.5,7616.9 7885.3,7617.2
  region net SA8: 7929.2,8108.9 7929.2,8104.9 7928.2,8104.8 7927.4,8104.6 7926.7,8104.2 7926.1,8103.7 7925,8102.4 7923.6,8100.9 7923.6,8112.9 7925,8111.5 7926.1,8110.2 7926.7,8109.7 7927.4,8109.3 7928.2,8109
  region net ALDO2: 7977.7,8038.3 7981.7,8034.2 7981.8,8033.5 7982,8032.8 7982.8,8031.4 7983.7,8029.9 7984.4,8028.6 7973.1,8032.7 7974.8,8033.7 7976.3,8035 7976.9,8035.7 7977.3,8036.5 7977.6,8037.4
  region net ALDO2: 7981.7,8017.2 7977.7,8013.1 7977.6,8014 7977.3,8014.9 7976.9,8015.6 7976.3,8016.4 7974.8,8017.6 7973.1,8018.7 7984.4,8022.8 7983.7,8021.4 7982.8,8020 7982,8018.6 7981.8,8017.9
  region net ALDO2: 7981.7,8037.3 7977.7,8037.3 7977.6,8038.4 7977.4,8039.2 7977,8039.8 7976.5,8040.4 7975.2,8041.5 7973.7,8042.9 7985.7,8042.9 7984.2,8041.5 7983,8040.4 7982.4,8039.8 7982.1,8039.2 7981.8,8038.4
  region net ALDO2: 7987.8,8057 7989,8052.6 7988.6,8052.1 7988.3,8051.4 7988,8049.6 7987.5,8046.3 7980.7,8056.2 7982.7,8055.9 7984.5,8055.7 7985.4,8055.8 7986.2,8056 7987,8056.4
  region net CPVDD: 6726,7949 6726,7959 6729,7959 6730.3,7959.3 6731.6,7960 6731.6,7948 6730.3,7948.8 6729,7949.1
  region net CPVEE: 6751.6,8004.3 6761.6,8004.3 6761.5,8001.3 6761.8,8000 6762.6,7998.7 6750.6,7998.7 6751.3,8000 6751.6,8001.3
  region net CPVEE: 6771.3,7964.9 6781.3,7964.9 6781.2,7961.9 6781.5,7960.6 6782.3,7959.3 6770.3,7959.3 6771,7960.6 6771.3,7961.9
  region net DCDC1: 6771.3,7846.8 6781.3,7846.8 6781.2,7843.8 6781.5,7842.5 6782.3,7841.2 6770.3,7841.2 6771,7842.5 6771.3,7843.8
  region net VRA1: 6800.9,7903.8 6790.9,7903.8 6791,7906.8 6790.7,7908.1 6789.9,7909.4 6801.9,7909.4 6801.2,7908.1 6800.9,7906.8
  region net VCC-RTC: 6803.2,7831.9 6803.2,7839.9 6804.6,7840.1 6806.1,7840.5 6807.6,7841.2 6808.8,7841.9 6808.8,7829.9 6807.6,7830.7 6806.1,7831.3 6804.6,7831.8
  region net DCDC4: 6812.2,7984.4 6822.2,7984.9 6822.2,7981.9 6822.5,7980.5 6823.3,7979.3 6811.3,7978.8 6812.1,7980.1 6812.3,7981.4
  region net DCDC4: 6822.2,7962.6 6812.2,7963.1 6812.3,7966.1 6812.1,7967.4 6811.3,7968.7 6823.3,7968.2 6822.5,7966.9 6822.2,7965.6
  region net DCDC4: 6812.2,8002.1 6822.2,8005.2 6822.2,8003.5 6822.2,8002 6822.7,8000.7 6823.1,8000.1 6823.7,7999.6 6812.1,7996.5 6812.6,7998 6812.6,7999.2 6812.4,8000.4
  region net DCDC4: 6822.2,7980.7 6812.2,7983.8 6812.4,7985.5 6812.6,7986.7 6812.6,7987.9 6812.1,7989.4 6823.7,7986.3 6823.1,7985.7 6822.7,7985.2 6822.2,7983.8 6822.2,7982.3
  region net DCDC4: 6812.2,7964.8 6822.2,7965.1 6822.2,7962 6822.5,7960.7 6823.3,7959.5 6811.3,7959.2 6812,7960.5 6812.3,7961.8
  region net DCDC4: 6822.2,7943 6812.2,7943.3 6812.3,7946.3 6812,7947.6 6811.3,7948.9 6823.3,7948.6 6822.5,7947.4 6822.2,7946
  region net DCDC4: 6812.2,7945.1 6822.2,7945.1 6822.1,7942.1 6822.4,7940.7 6823.2,7939.5 6811.2,7939.5 6812,7940.7 6812.3,7942.1
  region net VDD-SYSFB: 6851,7925.6 6859,7925.6 6859.1,7924.2 6859.6,7922.6 6860.2,7921.1 6861,7920 6849,7920 6849.8,7921.1 6850.4,7922.6 6850.8,7924.2
  region net VDD-CPU: 6877.4,7824.9 6877.4,7814.9 6874.4,7815 6873.1,7814.7 6871.8,7813.9 6871.8,7825.9 6873.1,7825.1 6874.4,7824.8
  region net VDD-CPU: 6875,7814.9 6880,7824.9 6881.4,7824.7 6882.9,7824.4 6884.3,7824.2 6885.6,7824.3 6880.6,7813.9 6880.2,7814.7 6879.7,7815.1 6879.1,7815.3 6878.5,7815.3 6876.9,7815.1
  region net VDD-CPU: 6902.7,7813.9 6902.7,7823.9 6905.7,7823.8 6907.1,7824.1 6908.3,7824.9 6908.3,7812.9 6907.1,7813.7 6905.7,7813.9
  region net ELDO3: 6924.9,8037.8 6924.9,8027.8 6921.9,8027.8 6920.6,8027.6 6919.3,8026.8 6919.3,8038.8 6920.6,8038 6921.9,8037.7
  region net VDD-CPU: 6922,7811.3 6922,7821.3 6925,7821.3 6926.4,7821.5 6927.6,7822.3 6927.6,7810.3 6926.4,7811.1 6925,7811.4
  region net VDD-CPU: 6926.5,7821.3 6922.3,7811.3 6919.5,7811.6 6918,7811.7 6916.7,7811.5 6920.9,7822.3 6921.3,7821.5 6921.9,7821.1 6922.5,7820.9 6923.1,7820.9 6924.7,7821.1
  region net VDD-CPU: 6941.7,7811.3 6939.5,7821.3 6941.1,7821.3 6942.6,7821.4 6943.9,7821.7 6944.5,7822.1 6945.1,7822.7 6947.3,7810.9 6945.9,7811.5 6944.7,7811.6 6943.4,7811.4
  region net VDD-CPU: 6943.8,7821.3 6943.8,7811.3 6940.8,7811.4 6939.5,7811.1 6938.2,7810.3 6938.2,7822.3 6939.5,7821.5 6940.8,7821.3
  region net VDD-CPUFB: 6977.1,7805.4 6969.1,7805.4 6968.9,7806.8 6968.5,7808.3 6967.9,7809.8 6967.1,7811 6979.1,7811 6978.3,7809.8 6977.7,7808.3 6977.2,7806.8
  region net AP-CK32K-OUT: 7001.9,7750.9 6999.1,7748.1 6998.3,7748.7 6997.5,7749.1 6996.8,7749.3 6996,7749.4 6994.3,7749.3 6992.3,7749.2 7000.8,7757.7 7000.7,7755.7 7000.6,7754 7000.6,7753.2 7000.8,7752.5 7001.2,7751.7
  region net SDQM0: 7018.5,7806.7 7021.5,7804.1 7020.9,7803.3 7020.5,7802.6 7020.3,7801.8 7020.3,7801 7020.4,7799.3 7020.5,7797.3 7011.8,7805.5 7013.8,7805.5 7015.5,7805.4 7016.2,7805.5 7017,7805.7 7017.7,7806.1
  region net SA2: 7018.8,7964.5 7021.6,7961.6 7020.9,7960.9 7020.5,7960.1 7020.3,7959.3 7020.3,7958.6 7020.4,7956.9 7020.5,7954.8 7012,7963.3 7014,7963.3 7015.7,7963.2 7016.5,7963.2 7017.2,7963.4 7018,7963.8
  region net SCS1: 7018.5,7924.8 7021.3,7922 7020.6,7921.2 7020.2,7920.4 7020.1,7919.7 7020,7918.9 7020.1,7917.2 7020.2,7915.2 7011.7,7923.7 7013.7,7923.6 7015.4,7923.5 7016.2,7923.6 7016.9,7923.8 7017.7,7924.2
  region net SDQM3: 7018.8,7885.7 7021.6,7882.9 7020.9,7882.1 7020.5,7881.4 7020.3,7880.6 7020.3,7879.8 7020.4,7878.1 7020.5,7876.1 7012,7884.6 7014,7884.5 7015.7,7884.4 7016.5,7884.5 7017.2,7884.7 7018,7885.1
  region net SDQ1: 7033.9,7786.5 7029.9,7786.9 7029.8,7787.9 7029.5,7788.7 7029.1,7789.4 7028.6,7790 7027.4,7791.1 7026,7792.5 7038,7792.1 7036.5,7790.7 7035.1,7789.6 7034.6,7789 7034.2,7788.3 7034,7787.5
  region net SDQ26: 7041,7830.7 7038.2,7827.8 7037.4,7828.5 7036.6,7828.9 7035.9,7829.1 7035.1,7829.1 7033.4,7829 7031.4,7829 7039.9,7837.5 7039.8,7835.4 7039.7,7833.7 7039.7,7833 7039.9,7832.2 7040.3,7831.4
  region net SDQ31: 7041.3,7870.3 7038.4,7867.5 7037.7,7868.1 7036.9,7868.5 7036.1,7868.7 7035.4,7868.8 7033.7,7868.7 7031.6,7868.6 7040.1,7877.1 7040.1,7875.1 7040,7873.4 7040,7872.6 7040.2,7871.9 7040.6,7871.1
  region net SA7: 7038,8002 7040.9,7999.4 7040.3,7998.6 7039.9,7997.8 7039.7,7997.1 7039.6,7996.3 7039.8,7994.6 7039.8,7992.6 7031.2,8000.9 7033.2,8000.9 7034.9,8000.7 7035.7,8000.8 7036.4,8001 7037.2,8001.4
  region net SDQ2: 7059.2,7772.7 7056.3,7769.8 7055.9,7770.1 7055.4,7770.1 7054.1,7769.8 7052.8,7769.2 7051.6,7769 7060.1,7777.4 7059.8,7776.2 7059.2,7774.9 7058.9,7773.7 7058.9,7773.1
  region net SDQ25: 7057.8,7846.1 7060.7,7843.2 7060,7842.5 7059.6,7841.7 7059.4,7840.9 7059.4,7840.2 7059.5,7838.5 7059.5,7836.4 7051.1,7844.9 7053.1,7844.9 7054.8,7844.8 7055.6,7844.8 7056.3,7845 7057.1,7845.4
  region net SODT0: 7057.8,7924.8 7060.7,7922 7060,7921.2 7059.6,7920.4 7059.4,7919.7 7059.4,7918.9 7059.5,7917.2 7059.5,7915.2 7051.1,7923.7 7053.1,7923.6 7054.8,7923.5 7055.6,7923.6 7056.3,7923.8 7057.1,7924.2
  region net SA4: 7058.1,7963.2 7061,7960.3 7060.3,7959.5 7059.9,7958.8 7059.7,7958 7059.7,7957.3 7059.8,7955.6 7059.8,7953.5 7051.3,7962 7053.4,7962 7055.1,7961.9 7055.8,7961.9 7056.6,7962.1 7057.3,7962.5
  region net SDQ29: 7058.1,7885.7 7061,7882.9 7060.3,7882.1 7059.9,7881.4 7059.7,7880.6 7059.7,7879.8 7059.8,7878.1 7059.8,7876.1 7051.3,7884.6 7053.4,7884.5 7055.1,7884.4 7055.8,7884.5 7056.6,7884.7 7057.3,7885.1
  region net SDQ3: 7060.9,7791 7057.9,7788.4 7057.1,7789.1 7056.3,7789.5 7055.6,7789.7 7054.8,7789.7 7053.2,7789.6 7051.1,7789.6 7059.8,7797.9 7059.8,7795.9 7059.6,7794.1 7059.7,7793.4 7059.9,7792.6 7060.3,7791.8
  region net SCKE0: 7263.6,8090.3 7263.6,8086.3 7262.6,8086.2 7261.8,8085.9 7261.1,8085.5 7260.5,8085 7259.4,8083.7 7258,8082.3 7258,8094.3 7259.4,8092.8 7260.5,8091.5 7261.1,8091 7261.8,8090.6 7262.6,8090.4
Bottom Layer:
  region net TWI0-CLK: 6615.7,7800.3 6615.7,7804.3 6616.7,7804.4 6617.6,7804.6 6618.2,7805 6618.8,7805.5 6619.9,7806.8 6621.3,7808.3 6621.3,7796.3 6619.9,7797.7 6618.8,7799 6618.2,7799.5 6617.6,7799.9 6616.7,7800.2
  region net USB0-ID-SOC: 6609.8,7716.8 6613.8,7716.8 6613.8,7715.8 6614.1,7715 6614.5,7714.3 6615,7713.7 6616.3,7712.6 6617.8,7711.2 6605.8,7711.2 6607.2,7712.6 6608.5,7713.7 6609,7714.3 6609.4,7715 6609.7,7715.8
  region net TWI0-SDA: 6616.5,7764.3 6616.5,7768.3 6617.5,7768.4 6618.3,7768.7 6619,7769.1 6619.6,7769.6 6620.7,7770.9 6622.1,7772.3 6622.1,7760.3 6620.7,7761.8 6619.6,7763.1 6619,7763.6 6618.3,7764 6617.5,7764.3
  region net MOTOR-DRV: 6616.1,7577.6 6612.1,7577.6 6612,7578.6 6611.8,7579.4 6611.4,7580.1 6610.9,7580.6 6609.6,7581.8 6608.1,7583.2 6620.1,7583.2 6618.6,7581.8 6617.4,7580.6 6616.8,7580.1 6616.5,7579.4 6616.2,7578.6
  region net MCSIB-D0N: 6617.3,8093.8 6621.3,8093.8 6621.4,8092.8 6621.7,8092 6622.1,8091.3 6622.6,8090.7 6623.9,8089.6 6625.3,8088.2 6613.3,8088.2 6614.8,8089.6 6616.1,8090.7 6616.6,8091.3 6617,8092 6617.3,8092.8
  region net CTP-RST: 6624,7668.4 6624,7672.4 6625,7672.5 6625.8,7672.8 6626.5,7673.2 6627.1,7673.7 6628.2,7675 6629.6,7676.4 6629.6,7664.4 6628.2,7665.9 6627.1,7667.2 6626.5,7667.7 6625.8,7668.1 6625,7668.4
  region net HP-DET: 6622,7929.5 6626,7929.5 6626.1,7928.5 6626.3,7927.7 6626.7,7927 6627.3,7926.4 6628.5,7925.3 6630,7923.9 6618,7923.9 6619.5,7925.3 6620.8,7926.4 6621.3,7927 6621.7,7927.7 6621.9,7928.5
  region net KD-EINT: 6632.9,7709.2 6636.9,7709.2 6637,7708.2 6637.3,7707.4 6637.7,7706.7 6638.2,7706.1 6639.5,7705 6640.9,7703.6 6628.9,7703.6 6630.4,7705 6631.7,7706.1 6632.2,7706.7 6632.6,7707.4 6632.9,7708.2
  region net MICIN2N: 6660.6,7908.7 6655.2,7908.9 6655.8,7909.7 6656.2,7910.5 6656.4,7911.4 6656.5,7912.3 6656.4,7914.2 6655.9,7916.1 6666.6,7910.6 6665.1,7910.2 6663.4,7909.9 6661.8,7909.4 6661.1,7909.1
  region net BT-UART-RX: 6665,7364.9 6665,7368.9 6666,7369 6666.8,7369.2 6667.5,7369.6 6668,7370.1 6669.1,7371.4 6670.6,7372.9 6670.6,7360.9 6669.1,7362.3 6668,7363.6 6667.5,7364.1 6666.8,7364.5 6666,7364.8
  region net BT-UART-CTS: 6664.9,7385.1 6664.9,7389.1 6666,7389.2 6666.8,7389.5 6667.4,7389.9 6668,7390.4 6669.1,7391.6 6670.5,7393.1 6670.5,7381.1 6669.1,7382.6 6668,7383.9 6667.4,7384.4 6666.8,7384.8 6666,7385
  region net BT-PCM-CLK: 6664,7406.2 6664,7410.2 6665,7410.3 6665.9,7410.6 6666.5,7411 6667.1,7411.5 6668.2,7412.7 6669.6,7414.2 6669.6,7402.2 6668.2,7403.7 6667.1,7405 6666.5,7405.5 6665.9,7405.9 6665,7406.1
  region net PH9: 6745.7,7833.9 6745.7,7837.9 6746.7,7838 6747.5,7838.3 6748.2,7838.7 6748.8,7839.2 6749.9,7840.5 6751.3,7841.9 6751.3,7829.9 6749.9,7831.4 6748.8,7832.7 6748.2,7833.2 6747.5,7833.6 6746.7,7833.9
  region net LRADC: 6747.4,7920.5 6749.8,7923.7 6750.5,7923.1 6751.3,7922.7 6752.1,7922.5 6752.9,7922.4 6754.6,7922.6 6756.6,7922.7 6748.6,7913.8 6748.6,7915.8 6748.7,7917.4 6748.6,7918.2 6748.4,7918.9 6748,7919.7
  region net MCSI-RST-R: 6747.7,8077.7 6750.6,8080.6 6751.3,8079.9 6752.1,8079.5 6752.8,8079.3 6753.6,8079.3 6755.3,8079.4 6757.3,8079.4 6748.9,8071 6748.9,8073 6749,8074.7 6749,8075.5 6748.8,8076.2 6748.4,8077
  region net CPVIN: 6751.6,7964.7 6761.6,7964.7 6761.5,7961.8 6761.8,7960.5 6762.6,7959.3 6750.6,7959.3 6751.3,7960.5 6751.6,7961.8
  region net CPUX-TDI: 6769.8,7787.5 6767.1,7790.4 6767.8,7791.2 6768.2,7792 6768.4,7792.7 6768.4,7793.5 6768.3,7795.1 6768.3,7797.2 6776.6,7788.6 6774.6,7788.6 6772.9,7788.8 6772.1,7788.7 6771.4,7788.5 6770.6,7788.1
  region net PH8: 6769.4,7866.3 6767.1,7869.6 6767.7,7870.3 6768.1,7871.1 6768.3,7871.8 6768.4,7872.6 6768.3,7874.2 6768.3,7876.2 6776.3,7867.3 6774.3,7867.4 6772.6,7867.6 6771.8,7867.5 6771,7867.3 6770.2,7866.9
  region net MCSI-SDA: 6767.1,8039.1 6770,8041.9 6770.7,8041.2 6771.5,8040.8 6772.3,8040.7 6773,8040.6 6774.7,8040.7 6776.8,8040.8 6768.3,8032.3 6768.3,8034.3 6768.4,8036 6768.4,8036.8 6768.2,8037.5 6767.8,8038.3
  region net CPVIN: 6781.2,7982.5 6771.2,7982.5 6771.3,7985.5 6771,7986.9 6770.2,7988.1 6782.2,7988.1 6781.5,7986.9 6781.2,7985.5
  region net VRA2: 6781.3,7903.8 6771.3,7903.8 6771.3,7906.8 6771,7908.1 6770.3,7909.4 6782.3,7909.4 6781.5,7908.1 6781.2,7906.8
  region net CPUX-TMS: 6784.9,7775.1 6785.2,7779.1 6786.2,7779.2 6787.1,7779.4 6787.7,7779.8 6788.3,7780.3 6789.4,7781.6 6790.8,7783 6790.5,7771 6789.1,7772.5 6788,7773.8 6787.4,7774.4 6786.7,7774.8 6785.9,7775
  region net CPUX-TDO: 6789.7,7748.1 6786.8,7750.9 6787.5,7751.7 6787.9,7752.4 6788.1,7753.2 6788.1,7754 6788,7755.7 6788,7757.7 6796.4,7749.2 6794.4,7749.3 6792.7,7749.4 6791.9,7749.3 6791.2,7749.1 6790.4,7748.7
  region net DLDO2: 6788.6,8028.3 6798.6,8027.5 6798.5,8024.5 6798.7,8023.2 6799.4,8021.9 6787.4,8022.7 6787.9,8023.3 6788.3,8024 6788.6,8025.3
  region net PH6: 6797.9,7864.4 6793.9,7864.4 6793.8,7865.4 6793.6,7866.2 6793.2,7866.9 6792.7,7867.5 6791.4,7868.6 6789.9,7870 6801.9,7870 6800.5,7868.6 6799.2,7867.5 6798.7,7866.9 6798.3,7866.2 6798,7865.4
  region net BT-PCM-SYNC: 6805,7790.5 6802.2,7787.7 6801.4,7788.3 6800.6,7788.7 6799.9,7788.9 6799.1,7789 6797.4,7788.9 6795.4,7788.8 6803.9,7797.3 6803.8,7795.3 6803.7,7793.6 6803.7,7792.8 6803.9,7792 6804.3,7791.3
  region net BT-PCM-DIN: 6812.2,7810.4 6809.3,7807.5 6808.5,7808.2 6807.8,7808.6 6807,7808.8 6806.3,7808.8 6804.6,7808.7 6802.5,7808.7 6811,7817.2 6811,7815.1 6810.9,7813.4 6810.9,7812.7 6811.1,7811.9 6811.5,7811.2
  region net VCC-PG: 6820.6,7388.2 6810.6,7388.2 6810.6,7391.2 6810.4,7392.6 6809.6,7393.8 6821.6,7393.8 6820.8,7392.6 6820.5,7391.2
  region net VCC-PG: 6810.6,7410 6820.6,7410 6820.5,7407 6820.8,7405.7 6821.6,7404.4 6809.6,7404.4 6810.4,7405.7 6810.6,7407
  region net CPVIN: 6835.3,8047.5 6832.2,8047.2 6829.2,8046.2 6826.5,8044.7 6824.1,8042.7 6822.2,8040.3 6820.8,8037.5 6815.8,8052.1 6820.8,8067.5 6822.2,8064.7 6824.1,8062.2 6826.5,8060.2 6829.2,8058.7 6832.2,8057.8 6835.3,8057.5 6835.3,8047.5
  region net CPVIN: 6824.4,8047.5 6824.4,8057.5 6827.4,8057.4 6828.8,8057.7 6830,8058.5 6830,8046.5 6828.8,8047.3 6827.4,8047.5
  region net VCC-USB: 6830.3,8083 6840.3,8083 6840.2,8080 6840.5,8078.7 6841.3,8077.4 6829.3,8077.4 6830.1,8078.7 6830.4,8080
  region net VDD-USB: 6846,8037.8 6846,8027.8 6843.1,8027.8 6841.8,8027.5 6840.6,8026.8 6840.6,8038.8 6841.8,8038 6843.1,8037.8
  region net BT-UART-TX: 6844.4,7790.5 6841.5,7787.7 6840.7,7788.3 6840,7788.7 6839.2,7788.9 6838.5,7789 6836.8,7788.8 6834.7,7788.8 6843.2,7797.3 6843.2,7795.3 6843.1,7793.6 6843.1,7792.8 6843.3,7792 6843.7,7791.3
  region net VCC-PC: 6885.6,8057.5 6885.6,8047.5 6882.6,8047.5 6881.2,8047.3 6880,8046.5 6880,8058.5 6881.2,8057.7 6882.6,8057.4
  region net PMU-SDA: 6908,7787.5 6905.2,7790.3 6905.8,7791.1 6906.2,7791.9 6906.4,7792.6 6906.5,7793.4 6906.3,7795.1 6906.3,7797.1 6914.8,7788.6 6912.7,7788.7 6911.1,7788.8 6910.3,7788.8 6909.5,7788.6 6908.8,7788.2
  region net GND: 6910,8083 6918,8083 6918.2,8081.6 6918.6,8080.1 6919.3,8078.6 6920,8077.4 6908,8077.4 6908.8,8078.6 6909.5,8080.1 6909.9,8081.6
  region net VCC-PL: 6919,7746.3 6909,7746.3 6909.1,7749.3 6908.8,7750.6 6908,7751.9 6920,7751.9 6919.3,7750.6 6919,7749.3
  region net EMMC-DS: 6920.3,8061.6 6923.2,8058.8 6922.5,8058 6922.1,8057.2 6921.9,8056.5 6921.9,8055.7 6922,8054 6922,8052 6913.5,8060.5 6915.6,8060.4 6917.3,8060.3 6918,8060.3 6918.8,8060.5 6919.5,8060.9
  region net GND: 6929.4,7874.6 6939.4,7874.6 6939.7,7871.9 6940.4,7869.3 6941.7,7866.9 6943.4,7864.8 6945.5,7863 6923.3,7863 6925.4,7864.8 6927.1,7866.9 6928.3,7869.3 6929.1,7871.9 6929.4,7874.6
  region net GND: 6939.4,7864.9 6929.4,7863.9 6929.4,7865.5 6929.4,7867 6929.1,7868.3 6928.7,7868.9 6928.2,7869.5 6940.1,7870.5 6939.5,7869.2 6939.3,7867.9
  region net ALDO1: 6942.5,7791.6 6942.5,7801.6 6945.5,7801.5 6946.9,7801.8 6948.1,7802.6 6948.1,7790.6 6946.9,7791.3 6945.5,7791.6
  region net GND: 6942.9,8077 6948.5,8082.7 6949.6,8081.8 6951,8081 6952.5,8080.4 6953.9,8080.1 6945.4,8071.7 6945.1,8073 6944.6,8074.5 6943.8,8075.9
  region net GND: 6936.5,7890 6936.5,7900 6939.9,7900.3 6943.1,7901.1 6946.2,7902.5 6949,7904.4 6951.5,7906.7 6951.5,7884.4 6948.2,7886.8 6944.5,7888.6 6940.5,7889.6 6936.5,7890
  region net GND: 6944.6,7900 6944.6,7890 6941.6,7890 6940.3,7889.8 6939,7889 6939,7901 6940.3,7900.2 6941.6,7899.9
  region net AP-NMI: 6963.8,7770.6 6961,7767.8 6960.2,7768.4 6959.5,7768.8 6958.7,7769 6957.9,7769.1 6956.2,7768.9 6954.2,7768.9 6962.7,7777.4 6962.7,7775.4 6962.5,7773.7 6962.6,7772.9 6962.8,7772.1 6963.2,7771.4
  region net DCDC1: 6957.6,8044 6964.6,8037 6962.5,8034.9 6961.7,8033.7 6961.4,8032.3 6952.9,8040.8 6954.4,8041.1 6955.5,8041.9
  region net DCDC5: 6991.2,7860.8 6991.2,7850.8 6988.3,7850.5 6985.6,7849.5 6983.1,7847.9 6981.1,7845.8 6979.6,7843.3 6979.6,7863 6983.4,7861.8 6987.3,7861.1 6991.2,7860.8
  region net DCDC5: 6980.3,7850.8 6980.3,7860.8 6983.3,7860.7 6984.6,7861 6985.9,7861.8 6985.9,7849.8 6984.6,7850.6 6983.3,7850.9
  region net DCDC5: 6987.7,7939.5 6987.7,7929.5 6984.3,7929.2 6980.9,7928.3 6977.8,7926.7 6975.1,7924.6 6972.7,7922 6972.7,7940.8 6980.2,7939.9 6987.7,7939.5
  region net DCDC5: 6980.3,7929.5 6980.3,7939.5 6983.3,7939.5 6984.6,7939.8 6985.9,7940.5 6985.9,7928.5 6984.6,7929.3 6983.3,7929.6
  region net AP-RESET: 6986.5,7807.1 6983.7,7809.9 6984.3,7810.7 6984.7,7811.5 6984.9,7812.2 6985,7813 6984.8,7814.7 6984.8,7816.7 6993.3,7808.3 6991.3,7808.3 6989.6,7808.4 6988.8,7808.4 6988,7808.2 6987.3,7807.8
  region net LCD-D23: 6999,8061.6 7001.6,8058.5 7001,8057.7 7000.6,8057 7000.4,8056.2 7000.3,8055.5 7000.4,8053.8 7000.4,8051.8 6992.2,8060.5 6994.2,8060.4 6995.9,8060.3 6996.7,8060.3 6997.5,8060.5 6998.3,8060.9
  region net GND: 7001.9,7790.3 6999.1,7787.5 6998.3,7788.1 6997.5,7788.5 6996.8,7788.7 6996,7788.8 6994.3,7788.6 6992.3,7788.6 7000.8,7797.1 7000.7,7795 7000.6,7793.4 7000.6,7792.6 7000.8,7791.8 7001.2,7791.1
  region net LCD-PWM: 6999.1,8041.9 7001.9,8039.1 7001.2,8038.3 7000.8,8037.5 7000.6,8036.8 7000.6,8036 7000.7,8034.3 7000.8,8032.3 6992.3,8040.8 6994.3,8040.7 6996,8040.6 6996.8,8040.7 6997.5,8040.8 6998.3,8041.2
  region net LCD-HSYNC: 7038.3,8081.3 7041.3,8078.6 7040.6,8077.8 7040.2,8077 7040,8076.3 7040,8075.5 7040.1,8073.8 7040.1,8071.8 7031.6,8080.1 7033.6,8080.1 7035.3,8080 7036,8080 7036.8,8080.2 7037.5,8080.6
  region net LCD-VSYNC: 7038.5,8061.6 7041.3,8058.8 7040.6,8058 7040.2,8057.2 7040,8056.5 7040,8055.7 7040.1,8054 7040.2,8052 7031.7,8060.5 7033.7,8060.4 7035.4,8060.3 7036.2,8060.3 7036.9,8060.5 7037.7,8060.9
  region net VCC-PL: 7056.8,7432.7 7056.4,7442.7 7059.4,7442.6 7060.7,7442.9 7062,7443.8 7062.4,7431.8 7061.2,7432.5 7059.8,7432.7
  region net LCD-CLK: 7069.5,8102.7 7073.5,8102.7 7073.6,8101.7 7073.9,8100.9 7074.3,8100.2 7074.8,8099.7 7076.1,8098.5 7077.5,8097.1 7065.5,8097.1 7067,8098.5 7068.3,8099.7 7068.8,8100.2 7069.2,8100.9 7069.4,8101.7
  region net LCD-DE: 7077.8,8081.3 7080.6,8078.4 7080,8077.7 7079.6,8076.9 7079.4,8076.1 7079.3,8075.4 7079.5,8073.7 7079.5,8071.7 7071,8080.1 7073.1,8080.1 7074.8,8080 7075.5,8080 7076.3,8080.2 7077,8080.6
  region net VCC-PL: 7078.8,7434.1 7072,7426.8 7069.8,7428.9 7068.7,7429.7 7067.2,7430 7075.5,7438.7 7075.9,7437.3 7076.6,7436.1
  region net LCD-CLK: 7126.1,8260.4 7126.1,8264.4 7127.1,8264.5 7128,8264.7 7128.6,8265.1 7129.2,8265.6 7130.3,8266.9 7131.7,8268.4 7131.7,8256.4 7130.3,8257.9 7129.2,8259.1 7128.6,8259.6 7128,8260 7127.1,8260.3
  region net LCD-DE: 7126.1,8239.7 7126.1,8243.7 7127.1,8243.8 7127.8,8244 7128.4,8244.4 7128.8,8245 7129.6,8246.3 7130.8,8247.8 7131.3,8235.8 7129.9,8237.2 7129,8238.5 7128.5,8239 7127.9,8239.3 7127.2,8239.6
  region net LCD-VSYNC: 7139.8,8276.2 7139.8,8280.2 7140.8,8280.3 7141.6,8280.6 7142.3,8281 7142.9,8281.5 7144,8282.7 7145.4,8284.2 7145.4,8272.2 7144,8273.7 7142.9,8275 7142.3,8275.5 7141.6,8275.9 7140.8,8276.1
  region net LCD-HSYNC: 7156.7,8292.2 7156.7,8296.2 7157.7,8296.3 7158.5,8296.6 7159.2,8297 7159.8,8297.5 7160.9,8298.8 7162.3,8300.2 7162.3,8288.2 7160.9,8289.7 7159.8,8291 7159.2,8291.5 7158.5,8291.9 7157.7,8292.2
  region net DCDC5: 7536.7,7773.5 7549.4,7774.9 7552.6,7772.2 7556.2,7770.3 7560.1,7769 7564.2,7768.5 7542,7757.6 7541.6,7761.8 7540.6,7766 7538.9,7769.9 7536.7,7773.5
  region net DCDC5: 7548.4,7775.8 7541.4,7768.8 7539.3,7770.9 7538.1,7771.7 7536.7,7772 7545.2,7780.5 7545.5,7779.1 7546.3,7777.9
  region net GND: 7589.9,7775.9 7604.2,7776 7601,7772.4 7598.3,7768.5 7576,7768.5 7579.9,7769.5 7583.5,7771.2 7586.9,7773.3 7589.9,7775.9
  region net GND: 7596.5,7768.3 7589.4,7775.4 7591.6,7777.5 7592.3,7778.6 7592.6,7780.1 7601.1,7771.6 7599.7,7771.2 7598.6,7770.5
  region net GND: 7664,7714.3 7674.3,7710.4 7672.9,7709.3 7671.6,7708.3 7671.1,7707.8 7670.9,7707.3 7670.8,7706.6 7671,7705.8 7660.3,7710.1 7661.4,7710.9 7662.3,7712 7663.2,7713.3
  region net GND: 7722.4,7819.5 7715.4,7826.6 7717.5,7828.7 7718.3,7829.8 7718.6,7831.3 7727.1,7822.8 7725.7,7822.4 7724.5,7821.7
  region net DCDC5: 7715.7,7775.5 7715.7,7785.5 7718.7,7785.4 7720,7785.7 7721.3,7786.5 7721.3,7774.5 7720,7775.2 7718.7,7775.5
  region net DCDC5: 7731.9,7740.6 7721.9,7740.6 7721.9,7743.6 7721.7,7744.9 7720.9,7746.2 7732.9,7746.2 7732.1,7744.9 7731.8,7743.6

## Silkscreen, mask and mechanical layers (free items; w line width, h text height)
Document Layer:
  lines w5: 6670.8,7322.7 6670.8,8283.3 8044.8,8283.3 8044.8,7322.7 6670.8,7322.7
